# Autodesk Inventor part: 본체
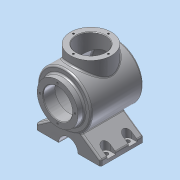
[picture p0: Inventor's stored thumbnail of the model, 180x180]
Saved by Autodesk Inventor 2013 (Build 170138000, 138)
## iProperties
Created: 2017-04
Part Number: 본체
Material: 알루미늄 6061
Document SubType Name: Modeling
Designer: dgall
Density: 2.71 g/cm^3
Mass: 1669.31 g
Surface Area: 1070.32 cm^2
Volume: 615.983 cm^3
Author: dgall
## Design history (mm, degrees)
sketch "스케치1"
  geometry: L1 (0, 0)-(120, 0); L2 (0, 27)-(22, 27); L3 (22, 27)-(22, 40); L4 (22, 40)-(101.916, 40); L5 (12, 50)-(12, 38); L6 (12, 38)-(0, 38); L7 (0, 27)-(0, 38); L8 (12, 50)-(108.336, 50); A1 r 113 centre (7, 0) between (120, 0) and (108.336, 50); A2 r 103 centre (7, 0) between (110, 0) and (101.916, 40)
  constraints: 16 end point, 4 point on circle, 3 perpendicular, 2 centre point, 2 parallel, 2 point on line, 1 horizontal
  dimensions: "d0" = 120 distance of L1.start L1.end; "d1" = 54 diameter of L2 L1; "d2" = 76 diameter of L6 L1; "d4" = 80 diameter of L4 L1; "d5" = 22 distance of L2.start L2.end; "d10" = 12 distance between parallel lines of L5 L7; "d11" = 100 diameter of L8 L1; "d12" = 113 radius of A1; "d13" = 0 distance from line of A1.centre L1; "d14" = 10 radial gap between concentric circles of A1 A2
revolve "회전1" sketch "스케치1" stored, may be unused: angle "d15" = 90 deg
node "작업 평면1"
sketch "스케치2"
  geometry: L1 (0, 0)-(0, -101.627); L2 (0, -82)-(-60, -82); L3 (-60, -82)-(-60, -72); L4 (-60, -72)-(-21.584, -45.101); L5 (60, -72)-(21.584, -45.101); L6 (60, -82)-(60, -72); L7 (0, -82)-(60, -82); A1 r 50 centre (0, 0) between (-21.584, -45.101) and (0, -50); 1 further point
  constraints: 14 end point, 3 symmetric about line, 2 perpendicular, 2 point on circle, 2 point on line, 2 vertical, 1 centre point, 1 coincident, 6 other
  dimensions: "d17" = 82 distance from line of point (0, 0) L2; "d18" = 10 distance of L2.end L3.end; "d19" = 55 deg angle of L4 L3; "d20" = 60 distance from line of L2.start L3
extrude "돌출1" join sketch "스케치2" distance "d21" = 80; taper "d22" = 0 deg
sketch "스케치3"
  geometry: L1 (60, -82)-(-60, -82) reference; C1 r 18 at (0, -82)
  constraints: 1 centre point, 1 midpoint
  dimensions: "d23" = 36 diameter of C1
extrude "돌출2" cut sketch "스케치3" stored distance "d25" = 80; taper "d26" = 0 deg
node "작업 평면2"
sketch "스케치4"
  geometry: L1 (50, 12)-(-50, 12) reference; C1 r 38 at (0, 62); 1 further point
  constraints: 1 centre point
  dimensions: "d28" = 76 diameter of C1; "d31" = 0 horizontal distance of point (0, 0) C1.centre; "d97" = 50 distance from line of L1 C1.centre
extrude "돌출3" join sketch "스케치4" stored distance "d33" = 80; taper "d34" = 0 deg
fillet "모깎기1" dims "d39" = 3
chamfer "모따기1" distance "d40" = 1; stored, may be unused: second distance "d41" = 2, angle "d42" = 45 deg
fillet "모깎기3" dims "d47" = 3
fillet "모깎기4" dims "d48" = 3
fillet "모깎기5" dims "d49" = 3
node "작업 평면3"
sketch "스케치6"
  geometry: L1 (57, 20)-(18, 20) reference; L2 (60, 23)-(60, 97) reference; L3 (18, 100)-(57, 100) reference; L4 (-60, 23)-(-60, 97) reference; L5 (-50, 32)-(-60, 32); L6 (-50, 48)-(-60, 48); L7 (-60, 48)-(-60, 32); L8 (-50, 72)-(-60, 72); L9 (-50, 88)-(-60, 88); L10 (-60, 88)-(-60, 72); L11 (50, 72)-(60, 72); L12 (50, 88)-(60, 88); L13 (60, 88)-(60, 72); L14 (50, 48)-(60, 48); L15 (50, 32)-(60, 32); L16 (60, 32)-(60, 48); A1 r 8 centre (50, 40) between (50, 48) and (50, 32); A2 r 8 centre (50, 80) between (50, 72) and (50, 88); A3 r 8 centre (-50, 80) between (-50, 72) and (-50, 88); A4 r 8 centre (-50, 40) between (-50, 32) and (-50, 48); 1 further point
  constraints: 24 end point, 9 perpendicular, 8 point on circle, 8 point on line, 8 tangent, 4 centre point, 3 equal radius, 2 collinear, 2 horizontal alignment, 1 parallel, 1 vertical alignment
  dimensions: "d51" = 20 distance from line of L1 A1.centre; "d52" = 10 distance from line of L2 A1.centre; "d53" = 16 diameter of A1; "d54" = 10 distance from line of L2 A2.centre; "d55" = 20 distance from line of A2.centre L3; "d56" = 10 distance from line of L4 A4.centre
extrude "돌출5" cut sketch "스케치6" stored distance "d57" = 30; taper "d58" = 0 deg
sketch "스케치7"
  geometry: L1 (50, 72)-(60, 72) reference; L2 (60, 88)-(60, 72) reference; L3 (60, 88)-(50, 88) reference; L4 (-60, 32)-(-50, 32) reference; L5 (-50, 48)-(-60, 48) reference; L6 (-60, 32)-(-60, 48) reference; L7 (-60, 72)-(-50, 72) reference; L8 (-50, 88)-(-60, 88) reference; L9 (-60, 72)-(-60, 88) reference; C1 r 4 at (50, 40); C2 r 4 at (-50, 80); C3 r 4 at (-50, 40); C4 r 4 at (50, 80); A1 r 8 centre (50, 40) between (50, 48) and (50, 32) reference; A2 r 8 centre (50, 80) between (50, 88) and (50, 72) reference; A3 r 8 centre (-50, 40) between (-50, 32) and (-50, 48) reference; A4 r 8 centre (-50, 40) between (-50, 32) and (-50, 48) reference; A5 r 8 centre (-50, 40) between (-50, 32) and (-50, 48) reference; A6 r 8 centre (-50, 80) between (-50, 72) and (-50, 88) reference; 1 further point
  constraints: 4 centre point, 4 coincident, 3 equal radius
  dimensions: "d59" = 8 diameter of C1
extrude "돌출6" cut sketch "스케치7" stored distance "d61" = 30; taper "d62" = 0 deg
sketch "스케치8"
  geometry: C1 r 38 at (0, 0) reference; C2 r 2 at (0, -32.5)
  constraints: 1 centre point
  dimensions: "d63" = 0 horizontal distance of C1.centre C2.centre; "d64" = 4 diameter of C2; "d65" = 32.5 distance of C1.centre C2.centre
hole "구멍1" sketch "스케치8" at (0, -32.5) diameter "d66" = 3.459; stored, may be unused: countersink angle "d70" = 90 deg, drill point angle "d72" = 118 deg; dims "d67" = 8, "d68" = 4, "d69" = 2, "d71" = 10
sketch "스케치9"
  geometry: C1 r 38 at (0, 0) reference; C2 r 2 at (0, -32.5); 1 further point
  constraints: 1 centre point
  dimensions: "d73" = 0 horizontal distance of C1.centre C2.centre; "d74" = 32.5 distance of C2.centre C1.centre; "d75" = 4 diameter of C2
hole "구멍2" sketch "스케치9" at (0, -32.5) diameter "d76" = 3.459; stored, may be unused: countersink angle "d80" = 90 deg, drill point angle "d82" = 118 deg; dims "d77" = 8, "d78" = 4, "d79" = 2, "d81" = 10
node "작업 평면5"
sketch "스케치11"
  geometry: L1 (-33.183, 4.803)-(33.183, 4.803); L2 (33.183, 4.803)-(33.183, -4.803); L3 (33.183, -4.803)-(-33.183, -4.803); L4 (-33.183, -4.803)-(-33.183, 4.803); L5 (-33.183, 0)-(33.183, 0); L6 (0, 4.803)-(0, -4.803); 1 further point
  constraints: 4 end point, 4 midpoint, 2 other
  dimensions: "d93" = 0 distance from line of point (0, 0) L6; "d94" = 0 distance from line of point (0, 0) L5
feature "엠보싱1" sketch "스케치11" dims "d17" = 82, "d18" = 10, "d19" = 55 deg, "d20" = 60, "d95" = 0.5, "d96" = 0
sketch "스케치12"
  geometry: C1 r 38 at (0, 0) reference; C2 r 27 at (0, 0); 1 further point
  constraints: 1 centre point, 1 coincident
  dimensions: "d98" = 54 diameter of C2
extrude "돌출7" cut sketch "스케치12" stored distance "d100" = 10; taper "d101" = 0 deg
fillet "모깎기6" dims "d105" = 3
chamfer "모따기3" distance "d106" = 1; stored, may be unused: second distance "d107" = 2, angle "d108" = 45 deg
node "솔리드1"
mirror "대칭1"
pattern_circular "원형 패턴2" dims angle "d87" = 360 deg
pattern_circular "원형 패턴3" dims angle "d103" = 360 deg
node "투영된 루프1"
node "투영된 루프2"
node "투영된 루프3"
node "투영된 루프4"
other parameters: "d27" = 65, "d50" = -76, "d92" = 120.5
